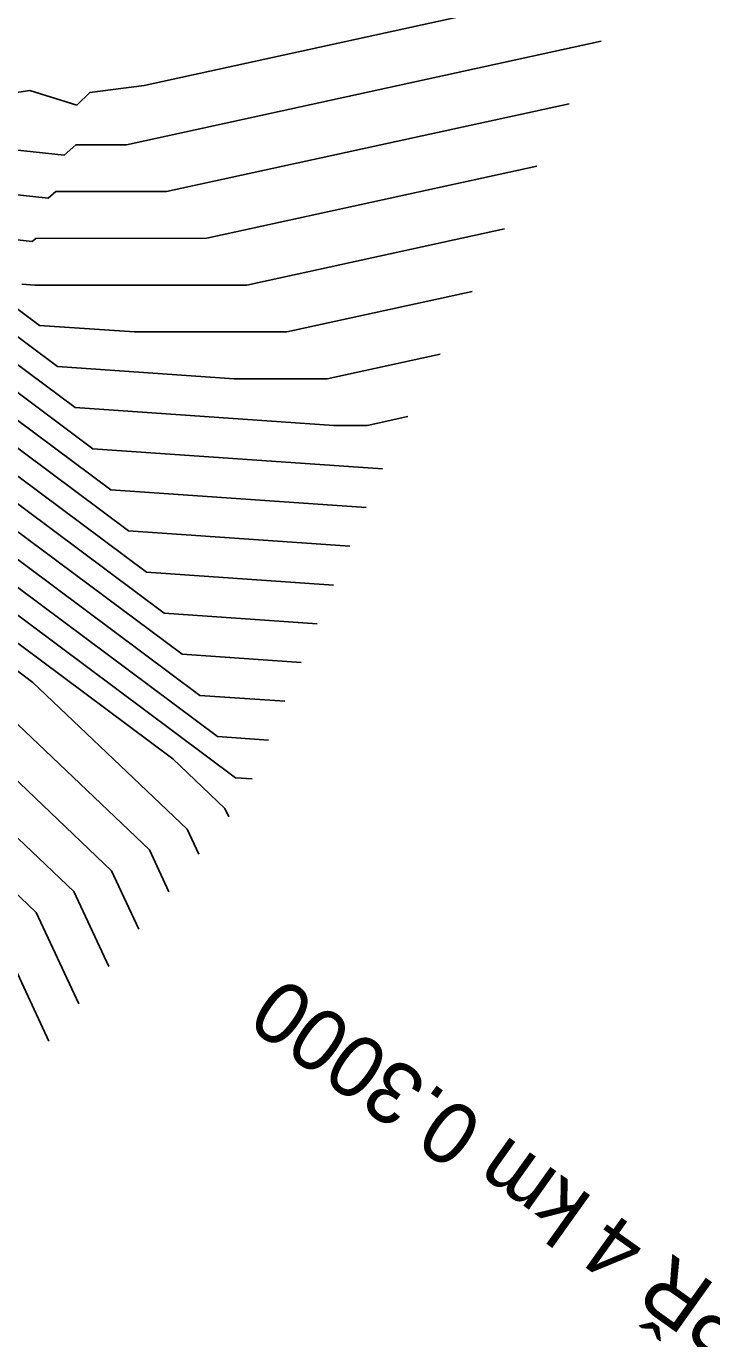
# Model space of a CAD drawing. Extents: x -549394 to -546608, y -1037055 to -1033629.
# Drawn here: x -546861.1 to -546760.3, y -1036097.5 to -1035904.5 of the extents above; entities that cross this region are included whole.
import ezdxf

# ---------------------------------------------------------------- set-up
doc = ezdxf.new("R2010")
doc.units = 0
for name, color, linetype in [('hlavni_vrst', 7, 'Continuous'), ('norm_vrst', 7, 'Continuous'), ('x_popis_pricne_rezy_C31', 7, 'Continuous')]:
    doc.layers.add(name, color=color, linetype=linetype)

msp = doc.modelspace()

# ---------------------------------------------------------------- linework, layer by layer
at = {"layer": 'hlavni_vrst'}
for p, q in [((-546781.29, -1035915.89), (-546840.45, -1035928.81)), ((-546857.86, -1035929.81), (-546863.74, -1035929.16)), ((-546856.73, -1035928.82), (-546857.86, -1035929.81)), ((-546840.45, -1035928.81), (-546856.73, -1035928.82)), ((-546853.89, -1035960.59), (-546871.88, -1035947.16)), ((-546840.8, -1035990.83), (-546887.26, -1035956.15)), ((-546815.86, -1035963.22), (-546853.89, -1035960.59)), ((-546805, -1035961.92), (-546810.95, -1035963.22)), ((-546810.95, -1035963.22), (-546815.86, -1035963.22)), ((-546839.53, -1036012.25), (-546902.64, -1035965.13)), ((-546859.63, -1036034.83), (-546905.4, -1035991.19)), ((-546818.29, -1035992.39), (-546840.8, -1035990.83)), ((-546831.88, -1036019.55), (-546839.53, -1036012.25)), ((-546831.3, -1036020.79), (-546831.88, -1036019.55)), ((-546853.35, -1036048.29), (-546859.63, -1036034.83))]:
    msp.add_line(p, q, dxfattribs=at)
at = {"layer": 'norm_vrst'}
for p, q in [((-546771.81, -1035897.48), (-546843.77, -1035913.2)), ((-546776.55, -1035906.68), (-546846.35, -1035921.93)), ((-546860.53, -1035913.97), (-546870.07, -1035915.34)), ((-546853.63, -1035916.1), (-546860.53, -1035913.97)), ((-546851.74, -1035914.26), (-546853.63, -1035916.1)), ((-546843.77, -1035913.2), (-546851.74, -1035914.26)), ((-546855.53, -1035923.47), (-546864.6, -1035922.47)), ((-546853.78, -1035921.93), (-546855.53, -1035923.47)), ((-546846.35, -1035921.93), (-546853.78, -1035921.93)), ((-546786.03, -1035925.09), (-546834.55, -1035935.69)), ((-546860.2, -1035936.15), (-546862.88, -1035935.86)), ((-546859.68, -1035935.7), (-546860.2, -1035936.15)), ((-546834.55, -1035935.69), (-546859.68, -1035935.7)), ((-546790.77, -1035934.3), (-546828.65, -1035942.57)), ((-546859.12, -1035948.5), (-546865.73, -1035943.56)), ((-546859.82, -1035942.58), (-546861.74, -1035942.45)), ((-546828.65, -1035942.57), (-546859.82, -1035942.58)), ((-546795.51, -1035943.5), (-546822.75, -1035949.45)), ((-546856.51, -1035954.54), (-546868.8, -1035945.36)), ((-546851.27, -1035966.64), (-546874.96, -1035948.96)), ((-546845.16, -1035949.46), (-546859.12, -1035948.5)), ((-546822.75, -1035949.45), (-546845.16, -1035949.46)), ((-546848.65, -1035972.69), (-546878.03, -1035950.75)), ((-546846.04, -1035978.74), (-546881.11, -1035952.55)), ((-546800.25, -1035952.71), (-546816.85, -1035956.34)), ((-546843.42, -1035984.79), (-546884.19, -1035954.35)), ((-546830.51, -1035956.34), (-546856.51, -1035954.54)), ((-546816.85, -1035956.34), (-546830.51, -1035956.34)), ((-546838.18, -1035996.88), (-546890.34, -1035957.94)), ((-546835.57, -1036002.93), (-546893.42, -1035959.74)), ((-546832.95, -1036008.98), (-546896.49, -1035961.54)), ((-546830.33, -1036015.03), (-546899.57, -1035963.33)), ((-546808.7, -1035969.58), (-546851.27, -1035966.64)), ((-546860.09, -1036001), (-546905.72, -1035966.93)), ((-546811.1, -1035975.28), (-546848.65, -1035972.69)), ((-546854.08, -1036031.78), (-546911.41, -1035977.11)), ((-546848.53, -1036028.72), (-546901.21, -1035978.49)), ((-546813.5, -1035980.98), (-546846.04, -1035978.74)), ((-546815.89, -1035986.69), (-546843.42, -1035984.79)), ((-546842.98, -1036025.66), (-546880.65, -1035989.74)), ((-546820.69, -1035998.09), (-546838.18, -1035996.88)), ((-546837.43, -1036022.61), (-546860.09, -1036001)), ((-546823.08, -1036003.79), (-546835.57, -1036002.93)), ((-546825.48, -1036009.49), (-546832.95, -1036008.98)), ((-546827.88, -1036015.2), (-546830.33, -1036015.03)), ((-546835.71, -1036026.29), (-546837.43, -1036022.61)), ((-546840.12, -1036031.79), (-546842.98, -1036025.66)), ((-546844.53, -1036037.29), (-546848.53, -1036028.72)), ((-546848.94, -1036042.79), (-546854.08, -1036031.78)), ((-546857.76, -1036053.79), (-546865.18, -1036037.89))]:
    msp.add_line(p, q, dxfattribs=at)

# ---------------------------------------------------------------- texts
at = {"layer": 'x_popis_pricne_rezy_C31'}
msp.add_text('PŘ 4 km 0.3000', height=9.0627, rotation=144.501, dxfattribs=at).set_placement((-546752.87, -1036094.5))

doc.saveas('drawing.dxf')
